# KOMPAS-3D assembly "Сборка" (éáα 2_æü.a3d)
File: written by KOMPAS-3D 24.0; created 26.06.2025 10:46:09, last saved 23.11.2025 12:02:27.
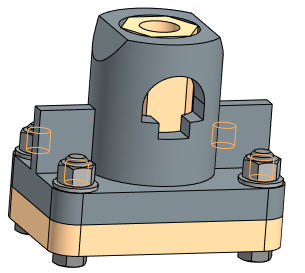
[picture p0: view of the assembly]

Document properties: Автор: Helen; Полное имя файла: C:\Для ноута\Инженерная графика\ППЭ 2025-2026\Варианты 1-38\Вариант 2 СБ\Решение 2\Вар 2 СБ\Вар 2_СБ.a3d

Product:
- Component [detail]: Сборка  | qty 4  | Масса: 0.008612; Автор: PC321; source file: Шайба 14.m3d
- Component [detail]: Сборка  | qty 4  | Масса: 0.02533; Автор: PC321; source file: Гайка М14.m3d
- Component [detail]: Болт М14x60 ГОСТ 15591-70  | qty 4  | Масса: 0.091885; source file: Болт М14x60 ГОСТ 15591-70.m3d
- Component [detail]: Основание  | designation Вариант 2  | qty 1  | Масса: 3.117293; Автор: Helen; source file: Основание _ Вариант 2.m3d
- Component [detail]: Nodes  | qty 1  | Масса: 4.02199; Автор: Helen; source file: Корпус вар2.m3d
- Part/product: Сборка
    Масса: 7.64259

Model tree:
1. Массив по сетке:1  (with: Элемент выдавливания:5, Операция без истории:1, Элемент выдавливания:1)  (4 pattern instances)
     Шаг 1 = 120; Угол раствора = 90; Шаг 2 = 70

Referenced files in C:\Для ноута\Инженерная графика\ППЭ 2025-2026\Варианты 1-38\Вариант 2 СБ\Решение 2\Вар 2 СБ\: Шайба 14.m3d, Гайка М14.m3d, Основание _ Вариант 2.m3d, Корпус вар2.m3d, Болт М14x60 ГОСТ 15591-70.m3d
Referenced files in C:\Для ноута\Инженерная графика\ППЭ 2025-2026\Варианты 1-38\Вариант 2 СБ\Вар 2 СБ\: Болт М14x60 ГОСТ 15591-70.m3d
Referenced files in D:\MY\WORK\MPEI\ППЭ_2025-2026\Варианты\Вар 1 СБ\: Гайка М14.m3d, Шайба 14.m3d
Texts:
  Сборка (1)
  Болт М14x60 ГОСТ 15591-70 (1)
  Вариант 2 Основание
